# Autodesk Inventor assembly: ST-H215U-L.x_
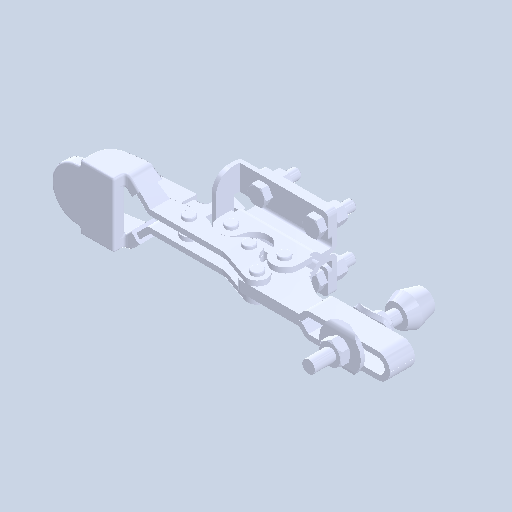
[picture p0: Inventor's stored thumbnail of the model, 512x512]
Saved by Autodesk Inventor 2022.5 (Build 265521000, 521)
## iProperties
Created: 2024-07
Part Number: ST-H215U-L.x_
Document SubType Name: Assembly
Designer: ImaoCorp
Author: ImaoCorp
Sending System: SOLIDWORKS 2022-2022290
MC: AMD64
MC_MODEL: Intel64 Family 6 Model 60 Stepping 3, GenuineIntel
OS: Windows_NT
FRU: Parasolid Version 33.1, build 260,  4-25-2022
FORMAT: text
GUISE: transmit
KEY: FILEST-H215U-L.x_t
DATE: Mon Jul 29 10:02:05 2024
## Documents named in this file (16)
- X:\14_SW2022-Inv2022\07_2024-10新製品(WHS)\OTC_データ\s\st-h215u-l\ST-H215U-L.x_.iam
- X:\14_SW2022-Inv2022\07_2024-10新製品(WHS)\OTC_データ\s\st-h215u-l\ST-H215U-L_01.ipt
- X:\14_SW2022-Inv2022\07_2024-10新製品(WHS)\OTC_データ\s\st-h215u-l\ST-H215U-L_02.ipt
- X:\14_SW2022-Inv2022\07_2024-10新製品(WHS)\OTC_データ\s\st-h215u-l\ST-H215U-L_03.ipt
- X:\14_SW2022-Inv2022\07_2024-10新製品(WHS)\OTC_データ\s\st-h215u-l\ST-H215U-L_04.ipt
- X:\14_SW2022-Inv2022\07_2024-10新製品(WHS)\OTC_データ\s\st-h215u-l\ST-H215U-L_05.ipt
- X:\14_SW2022-Inv2022\07_2024-10新製品(WHS)\OTC_データ\s\st-h215u-l\ST-H215U-L_06.ipt
- X:\14_SW2022-Inv2022\07_2024-10新製品(WHS)\OTC_データ\s\st-h215u-l\ST-H215U-L_07.ipt
- X:\14_SW2022-Inv2022\07_2024-10新製品(WHS)\OTC_データ\s\st-h215u-l\ST-H215U-L_08.ipt
- X:\14_SW2022-Inv2022\07_2024-10新製品(WHS)\OTC_データ\s\st-h215u-l\ST-H215U-L_09.ipt
- X:\14_SW2022-Inv2022\07_2024-10新製品(WHS)\OTC_データ\s\st-h215u-l\ST-H215U-L_10.ipt
- X:\14_SW2022-Inv2022\07_2024-10新製品(WHS)\OTC_データ\s\st-h215u-l\ST-H215U-L_11.ipt
- X:\14_SW2022-Inv2022\07_2024-10新製品(WHS)\OTC_データ\s\st-h215u-l\ST-H215U-L_12.ipt
- X:\14_SW2022-Inv2022\07_2024-10新製品(WHS)\OTC_データ\s\st-h215u-l\ST-H215U-L_13.ipt
- X:\14_SW2022-Inv2022\07_2024-10新製品(WHS)\OTC_データ\s\st-h215u-l\ST-H215U-L_14.ipt
- X:\14_SW2022-Inv2022\07_2024-10新製品(WHS)\OTC_データ\s\st-h215u-l\ST-H215U-L_15.ipt
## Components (15 placed, 15 different names)
1. ST-H215U-L_01
2. ST-H215U-L_02
3. ST-H215U-L_03
4. ST-H215U-L_04
5. ST-H215U-L_05
6. ST-H215U-L_06
7. ST-H215U-L_07
8. ST-H215U-L_08
9. ST-H215U-L_09
10. ST-H215U-L_10
11. ST-H215U-L_11
12. ST-H215U-L_12
13. ST-H215U-L_13
14. ST-H215U-L_14
15. ST-H215U-L_15
